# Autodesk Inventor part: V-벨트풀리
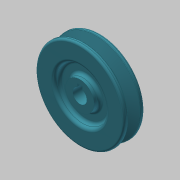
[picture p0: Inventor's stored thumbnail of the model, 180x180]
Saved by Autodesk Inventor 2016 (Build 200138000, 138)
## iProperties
Created: 2019-09
Part Number: V-벨트풀리
Material: 알루미늄 6061
Document SubType Name: Modeling
Designer: mduedu
Density: 1 g/cm^3
Appearance: 커뎃 파란색
Author: mduedu
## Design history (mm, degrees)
sketch "스케치1"
  geometry: L1 (-10, 0)-(10, 0); L2 (10, 0)-(10, 43.5); L3 (10, 43.5)-(-10, 43.5); L4 (-10, 43.5)-(-10, 0); L5 (0, 0)-(0, 43.5); L6 (-5.976, 43.5)-(-2.154, 31); L7 (-2.154, 31)-(2.154, 31); L8 (2.154, 31)-(5.976, 43.5); L9 (-10, 39)-(10, 39); 3 further points
  constraints: 18 end point, 8 point on line, 3 perpendicular, 2 midpoint, 2 parallel, 1 coincident, 1 horizontal, 1 other
  dimensions: "d0" = 87 diameter of L3 L1; "d3" = 12.5 distance between parallel lines of L7 L3; "d4" = 34 deg angle of L8 L6; "d5" = 20 distance between parallel lines of L2 L4; "d6" = 8 distance between parallel lines of L9 L7; "d7" = 9.2 distance of point (4.6, 39) point (-4.6, 39)
revolve "회전1" sketch "스케치1" stored, may be unused: angle "d8" = 90 deg
sketch "스케치2"
  geometry: C1 r 14 at (0, 0); C2 r 25 at (0, 0); 1 further point
  constraints: 2 centre point, 2 coincident
  dimensions: "d9" = 28 diameter of C1; "d10" = 50 diameter of C2
extrude "돌출1" cut sketch "스케치2" distance "d11" = 6; taper "d12" = 0 deg
fillet "모깎기1" dims "d13" = 3
fillet "모깎기2" dims "d14" = 3
fillet "모깎기3" dims "d15" = 0.5, "d16" = 1, "d17" = 2
sketch "스케치3"
  geometry: L1 (-2.5, 6.538)-(2.5, 6.538); L2 (2.5, 6.538)-(2.5, 9.3); L3 (2.5, 9.3)-(-2.5, 9.3); L4 (-2.5, 9.3)-(-2.5, 6.538); A1 r 7 centre (0, 0) between (-2.5, 6.538) and (2.5, 6.538); 1 further point
  constraints: 8 end point, 2 parallel, 2 point on circle, 1 centre point, 1 coincident, 1 horizontal, 1 perpendicular
  dimensions: "d18" = 14 diameter of A1; "d20" = 5 distance of L2.end L3.end; "d21" = 16.3 dimension on A1 L3
extrude "돌출2" cut sketch "스케치3" stored distance "d22" = 6; taper "d23" = 0 deg
node "솔리드1"
mirror "대칭1"
